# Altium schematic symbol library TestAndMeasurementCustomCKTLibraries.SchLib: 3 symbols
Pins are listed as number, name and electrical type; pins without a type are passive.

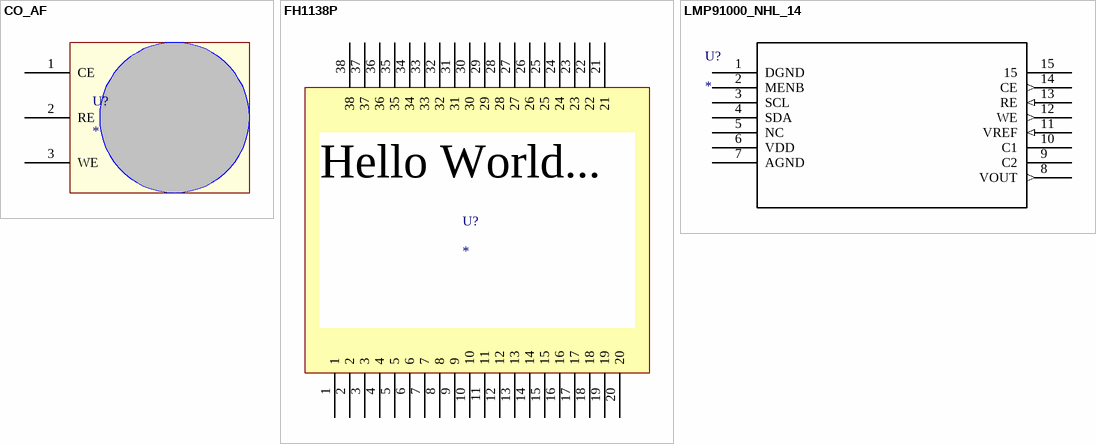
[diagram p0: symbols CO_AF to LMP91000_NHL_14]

## CO_AF
designator U?
footprint CO_AF
pins: 1 CE, 2 RE, 3 WE

## FH1138P
designator U?
footprint FH1138P
pins: 1, 2, 3, 4, 5, 6, 7, 8, 9, 10, 11, 12, 13, 14, 15, 16, 17, 18, 19, 20, 21, 22, 23, 24, 25, 26, 27, 28, 29, 30, 31, 32, 33, 34, 35, 36, 37, 38

## LMP91000_NHL_14
designator U?
Imported; Manufacturer: Texas Instruments; Manufacturer_Part_Number: lmp91000_nhl_14; basePN: LMP91000; NSC_PackageReference: SDA14B
footprint SDA14B
pins: 1 DGND (power), 2 MENB, 3 SCL, 4 SDA, 5 NC, 6 VDD (power), 7 AGND (power), 8 VOUT (out), 9 C2, 10 C1, 11 VREF (in), 12 WE (out), 13 RE (in), 14 CE (out), 15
